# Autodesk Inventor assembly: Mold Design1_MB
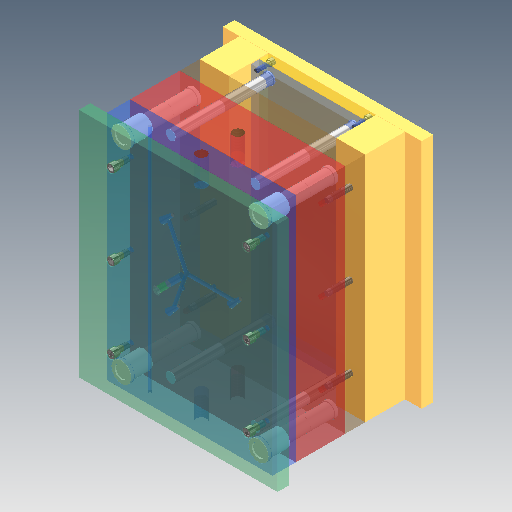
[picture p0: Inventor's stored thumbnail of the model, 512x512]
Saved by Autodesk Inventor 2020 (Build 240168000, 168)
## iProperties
Created: 2019-07
Part Number: Mold Design1_MB
Document SubType Name: Assembly
Designer: LENOVO-CADCIM
Author: LENOVO-CADCIM
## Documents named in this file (16)
- D:\Autodesk Inventor_2020\Resources\Resources\Inventor_2020_tut\Inventor_2020_tut\c19_Inv_2019_tut\MB\FUTABA_SA-S 1\Mold Design1_MB.iam
- C:\Users\LENOVO-CADCIM\Documents\Inventor\Content Center Files\R2020\en-US\JIS 1176\JIS 1176 M12x40.ipt
- C:\Users\LENOVO-CADCIM\Documents\Inventor\Content Center Files\R2020\en-US\GBA\M-GBA 40x69.ipt
- D:\Autodesk Inventor_2020\Resources\Resources\Inventor_2020_tut\Inventor_2020_tut\c19_Inv_2019_tut\MB\FUTABA_SA-S 1\Mold Design1_MB_SA-SB1.ipt
- D:\Autodesk Inventor_2020\Resources\Resources\Inventor_2020_tut\Inventor_2020_tut\c19_Inv_2019_tut\MB\FUTABA_SA-S 1\Mold Design1_MB_SA-SB2.ipt
- D:\Autodesk Inventor_2020\Resources\Resources\Inventor_2020_tut\Inventor_2020_tut\c19_Inv_2019_tut\MB\FUTABA_SA-S 1\Mold Design1_MB_SA-EP.ipt
- C:\Users\LENOVO-CADCIM\Documents\Inventor\Content Center Files\R2020\en-US\GPA\M-GPA40x217x69.ipt
- D:\Autodesk Inventor_2020\Resources\Resources\Inventor_2020_tut\Inventor_2020_tut\c19_Inv_2019_tut\MB\FUTABA_SA-S 1\Mold Design1_MB_SA-ERP.ipt
- D:\Autodesk Inventor_2020\Resources\Resources\Inventor_2020_tut\Inventor_2020_tut\c19_Inv_2019_tut\MB\FUTABA_SA-S 1\Mold Design1_MB_SA-BCP.ipt
- C:\Users\LENOVO-CADCIM\Documents\Inventor\Content Center Files\R2020\en-US\JIS 1176\JIS 1176 M16x35.ipt
- D:\Autodesk Inventor_2020\Resources\Resources\Inventor_2020_tut\Inventor_2020_tut\c19_Inv_2019_tut\MB\FUTABA_SA-S 1\Mold Design1_MB_RPN.ipt
- D:\Autodesk Inventor_2020\Resources\Resources\Inventor_2020_tut\Inventor_2020_tut\c19_Inv_2019_tut\MB\FUTABA_SA-S 1\Mold Design1_MB_SA-S-AP.ipt
- D:\Autodesk Inventor_2020\Resources\Resources\Inventor_2020_tut\Inventor_2020_tut\c19_Inv_2019_tut\MB\FUTABA_SA-S 1\Mold Design1_MB_SA-S-BP.ipt
- D:\Autodesk Inventor_2020\Resources\Resources\Inventor_2020_tut\Inventor_2020_tut\c19_Inv_2019_tut\MB\FUTABA_SA-S 1\Mold Design1_MB_SA-TCP.ipt
- D:\Autodesk Inventor_2020\Resources\Resources\Inventor_2020_tut\Inventor_2020_tut\c19_Inv_2019_tut\MB\FUTABA_SA-S 1\Mold Design1_MB_SA-SP.ipt
- C:\Users\LENOVO-CADCIM\Documents\Inventor\Content Center Files\R2020\en-US\JIS 1176\JIS 1176 M16x210.ipt
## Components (37 placed, 15 different names)
1. Mold Design1_MB_SA-SB1:1 — Flush:1, Flush:3, Mate:1, Mate:5
2. Mold Design1_MB_SA-SB2:2 — Flush:2, Flush:4, Mate:2, Mate:6
3. Mold Design1_MB_SA-EP:1 — Insert:1, Flush:5, Flush:6, Ejection, Mate:4
4. Mold Design1_MB_SA-ERP:1 — Insert:7, Flush:7, Flush:8, Mate:4
5. Mold Design1_MB_SA-BCP:1 — Insert:8, Ejection, Flush:9, Flush:10, Mate:5, Mate:6
6. Mold Design1_MB_SA-S-AP:1 — Insert:2, Insert:5, Flush:11, Flush:12, Mate:7, PL1, Flush:19
7. Mold Design1_MB_SA-S-BP:1 — Insert:3, Insert:4, Flush:13, Flush:14, PL1, Mate:9
8. Mold Design1_MB_SA-TCP:1 — Insert:6, Mate:7, Flush:15, Flush:16
9. Mold Design1_MB_SA-SP:1 — Mate:1, Mate:2, Flush:17, Flush:18, Mate:9
10. GPA 40x217x69:1 — Insert:3
11. GPA 40x217x69:3
12. JIS 1176 M16x35:1 — Insert:6
13. JIS 1176 M16x35:2
14. JIS 1176 M16x35:3
15. JIS 1176 M16x35:4
16. JIS 1176 M16x35:5
17. JIS 1176 M16x35:6
18. JIS 1176 M12x40:1 — Insert:1
19. JIS 1176 M12x40:2
20. JIS 1176 M12x40:3
21. JIS 1176 M12x40:4
22. JIS 1176 M16x210:1 — Insert:8
23. JIS 1176 M16x210:2
24. JIS 1176 M16x210:3
25. JIS 1176 M16x210:4
26. JIS 1176 M16x210:5
27. JIS 1176 M16x210:6
28. GBA 40x69:1 — Insert:2
29. GBA 40x69:3
30. GPA 40x217x69:2 — Insert:4
31. GPA 40x217x69:4
32. Mold Design1_MB_RPN:1 — Insert:7
33. Mold Design1_MB_RPN:2
34. Mold Design1_MB_RPN:3
35. Mold Design1_MB_RPN:4
36. GBA 40x69:2 — Insert:5
37. GBA 40x69:4
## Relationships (36: Flush 19, Mate 9, Insert 8)
- Insert:1: Mold Design1_MB_SA-EP:1 ↔ JIS 1176 M12x40:1
- Insert:2: Mold Design1_MB_SA-S-AP:1 ↔ GBA 40x69:1
- Insert:3: Mold Design1_MB_SA-S-BP:1 ↔ GPA 40x217x69:1
- Insert:4: Mold Design1_MB_SA-S-BP:1 ↔ GPA 40x217x69:2
- Insert:5: Mold Design1_MB_SA-S-AP:1 ↔ GBA 40x69:2
- Insert:6: Mold Design1_MB_SA-TCP:1 ↔ JIS 1176 M16x35:1
- Insert:7: Mold Design1_MB_SA-ERP:1 ↔ Mold Design1_MB_RPN:1
- Insert:8: Mold Design1_MB_SA-BCP:1 ↔ JIS 1176 M16x210:1
- Flush:1: Mold Design1_MB_SA-SB1:1
- Flush:2: Mold Design1_MB_SA-SB2:2
- Flush:3: Mold Design1_MB_SA-SB1:1
- Flush:4: Mold Design1_MB_SA-SB2:2
- Mate:1: Mold Design1_MB_SA-SB1:1 ↔ Mold Design1_MB_SA-SP:1
- Mate:2: Mold Design1_MB_SA-SB2:2 ↔ Mold Design1_MB_SA-SP:1
- Flush:5: Mold Design1_MB_SA-EP:1
- Flush:6: Mold Design1_MB_SA-EP:1
- Ejection [Mate]: Mold Design1_MB_SA-EP:1 ↔ Mold Design1_MB_SA-BCP:1
- Flush:7: Mold Design1_MB_SA-ERP:1
- Flush:8: Mold Design1_MB_SA-ERP:1
- Mate:4: Mold Design1_MB_SA-EP:1 ↔ Mold Design1_MB_SA-ERP:1
- Flush:9: Mold Design1_MB_SA-BCP:1
- Flush:10: Mold Design1_MB_SA-BCP:1
- Mate:5: Mold Design1_MB_SA-SB1:1 ↔ Mold Design1_MB_SA-BCP:1
- Mate:6: Mold Design1_MB_SA-SB2:2 ↔ Mold Design1_MB_SA-BCP:1
- Flush:11: Mold Design1_MB_SA-S-AP:1
- Flush:12: Mold Design1_MB_SA-S-AP:1
- Mate:7: Mold Design1_MB_SA-S-AP:1 ↔ Mold Design1_MB_SA-TCP:1
- Flush:13: Mold Design1_MB_SA-S-BP:1
- Flush:14: Mold Design1_MB_SA-S-BP:1
- PL1 [Mate]: Mold Design1_MB_SA-S-AP:1 ↔ Mold Design1_MB_SA-S-BP:1
- Flush:15: Mold Design1_MB_SA-TCP:1
- Flush:16: Mold Design1_MB_SA-TCP:1
- Flush:17: Mold Design1_MB_SA-SP:1
- Flush:18: Mold Design1_MB_SA-SP:1
- Mate:9: Mold Design1_MB_SA-S-BP:1 ↔ Mold Design1_MB_SA-SP:1
- Flush:19: Mold Design1_MB_SA-S-AP:1
